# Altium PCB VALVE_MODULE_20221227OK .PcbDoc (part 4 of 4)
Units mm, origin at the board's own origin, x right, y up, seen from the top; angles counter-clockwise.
Board outline 260.15 x 142.01 mm, 2 copper layers (Top Layer, Bottom Layer); 455 components, 212 nets, 1302 pads, 385 vias.
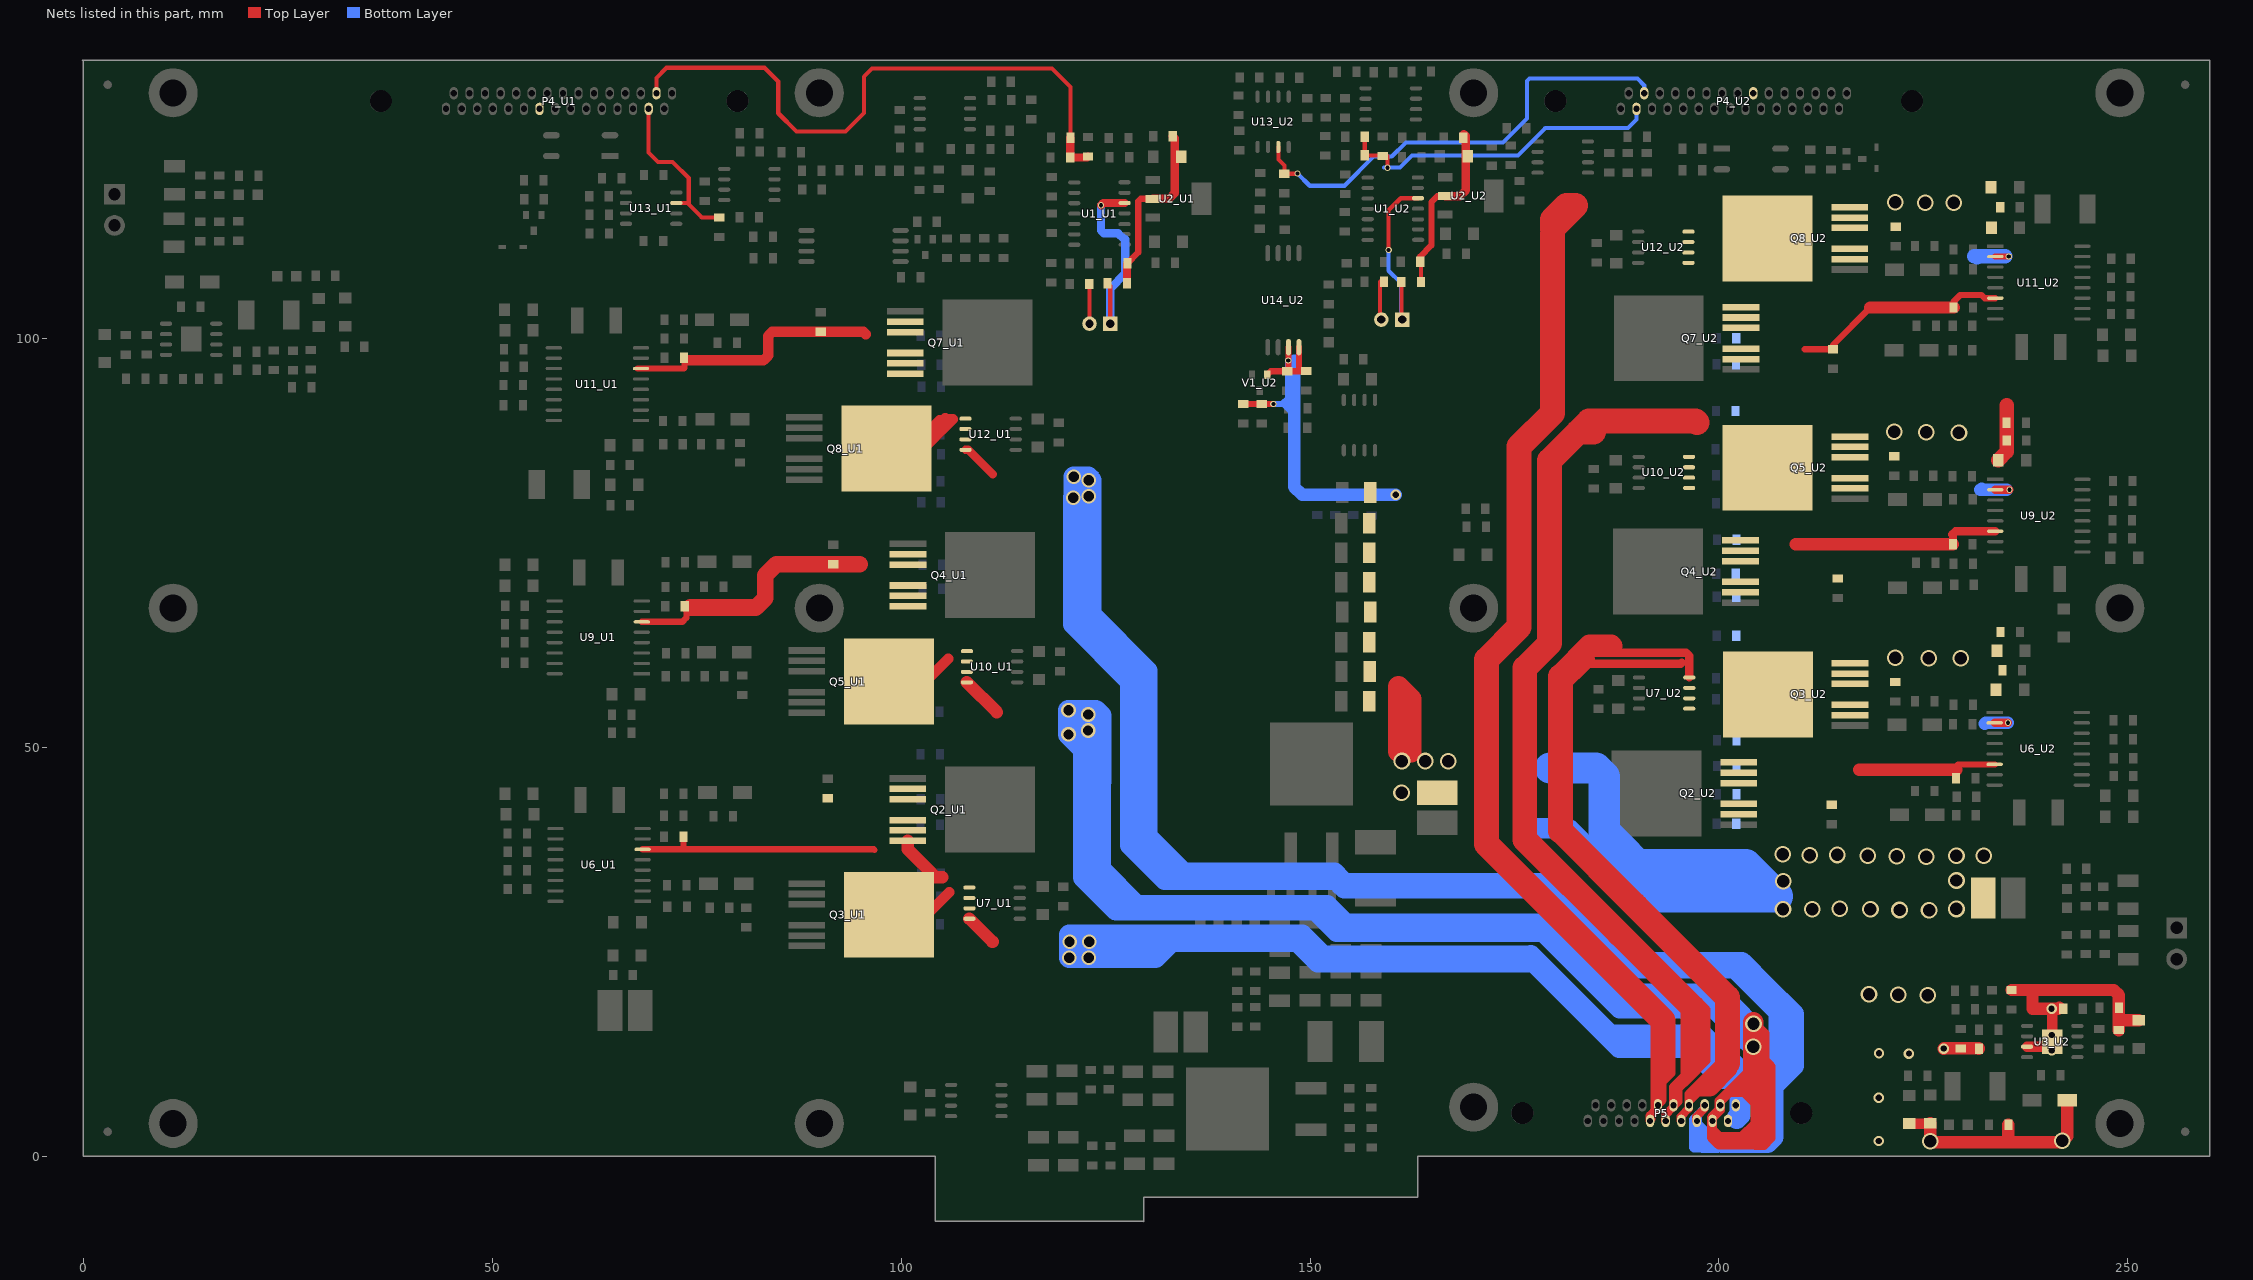
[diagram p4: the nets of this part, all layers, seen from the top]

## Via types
v1: diameter 0.762, hole 0.508, Top Layer to Bottom Layer, 142 vias
v2: diameter 2.032, hole 1.524, Top Layer to Bottom Layer, 140 vias
v3: diameter 1.27, hole 0.762, Top Layer to Bottom Layer, 77 vias
v4: diameter 1.27, hole 0.711, Top Layer to Bottom Layer, 14 vias
v5: diameter 1.778, hole 1.27, Top Layer to Bottom Layer, 12 vias

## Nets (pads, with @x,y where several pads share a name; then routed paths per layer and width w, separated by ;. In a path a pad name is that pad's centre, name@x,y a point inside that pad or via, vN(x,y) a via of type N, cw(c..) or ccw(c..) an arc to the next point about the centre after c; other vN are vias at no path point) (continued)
PGND_U2: C15_U2.2 C16_U2.2 C17_U2.2 C18_U2.2 C19_U2.2 C20_U2.2 C21_U2.2 C22_U2.2 C24_U2.2 C25_U2.1 C26_U2.1 C27_U2.1 C29_U2.1 C30_U2.1 C69_U2.1 C70_U2.2 C71_U2.2 C72_U2.2 C73_U2.2 C74_U2.2 C75_U2.2 C76_U2.2 C77_U2.2 C78_U2.2 C79_U2.2 C80_U2.2 C81_U2.2 C82_U2.2 C83_U2.2 C84_U2.2 C85_U2.2 C86_U2.2 C87_U2.2 C88_U2.2 C89_U2.2 C90_U2.2 C91_U2.2 C92_U2.2 C93_U2.2 C106_U2.2 C107_U2.2 C108_U2.2 C109_U2.2 C110_U2.2 C111_U2.2 C112_U2.2 C113_U2.2 D2_U2.1 Q3_U2.2 Q3_U2.3 Q3_U2.5 Q3_U2.6 Q3_U2.7 Q5_U2.2 Q5_U2.3 Q5_U2.5 Q5_U2.6 Q5_U2.7 Q8_U2.2 Q8_U2.3 Q8_U2.5 Q8_U2.6 Q8_U2.7 R16_U2.2 R21_U2.2 R22_U2.1 R24_U2.2 R25_U2.1 R37_U2.1 R54_U2.1 R68_U2.1 R76_U2.2 R80.2 U3_U2.7 U3_U2.9 U6_U2.2 U9_U2.2 U11_U2.2 U14_U2.3 U14_U2.4 V1_U2.1 | length 246.4
  Top Layer w0.762: C30_U2.1@141.859,91.948 C29_U2.1@144.12,91.948 145.517,91.948 145.542,91.973 v1(145.517,91.973) ; V1_U2.1@144.78,95.529 145.212,95.961 C69_U2.1@147.193,95.961 ; U14_U2.3@147.371,98.908 147.371,96.139 C69_U2.1@147.193,95.961 ; U14_U2.4@148.641,98.908 148.641,96.012 148.59,95.961 ; R76_U2.2@149.555,95.987 149.53,95.961 148.59,95.961 ; U11_U2.2@233.782,109.982 v1(235.433,109.982) ; C69_U2.1@147.193,95.961 148.59,95.961
  Top Layer w1.016: U6_U2.2@233.705,52.984 235.309,52.984 v1(235.32,52.995) ; U9_U2.2@233.782,81.483 v1(235.509,81.483)
  Top Layer w1.27: C22_U2.2@223.241,3.988 225.755,3.988 C21_U2.2@225.806,4.039 ; U3_U2.7@237.668,13.386 240.132,13.386 U3_U2.9@240.741,13.995 240.741,17.958 v3(240.665,18.034)
  Top Layer w1.524: C21_U2.2@225.806,4.039 225.806,1.829 225.933,1.702 235.356,1.702 ; v3(227.482,13.157) 227.508,13.183 R25_U2.1@229.54,13.183 231.75,13.183 C27_U2.1@231.775,13.157 ; R16_U2.2@235.382,3.861 235.382,1.727 235.356,1.702 ; R22_U2.1@235.763,20.32 237.922,20.32 ; C26_U2.1@241.605,18.161 241.478,18.034 v3(240.665,18.034) 238.328,18.034 238.328,19.914 237.922,20.32 ; D2_U2.1@242.57,6.858 242.57,2.438 241.833,1.702 235.356,1.702 ; C25_U2.1@248.869,15.418 248.869,16.535 ; C24_U2.2@251.333,16.612 248.945,16.612 248.869,16.535 ; 237.922,20.32 248.26,20.32 248.895,19.685 R24_U2.2@248.895,18.136 248.869,18.11 248.869,16.535
  Top Layer w1.778: C108_U2.2@234.137,85.09 235.204,86.157 235.204,91.796
  Top Layer w2.54: 160.807,49.479 160.807,57.429 162.331,55.905 162.331,49.378
  Bottom Layer w0.762: v1(145.517,91.973) 146.634,91.973 ; 148.057,90.627 146.71,91.973 ; 148.057,91.567 147.65,91.973 146.71,91.973 ; 148.057,97.257 148.031,97.282 v1(147.345,97.282) 147.345,92.685 146.634,91.973 ; 146.634,91.973 146.71,91.973
  Bottom Layer w1.524: 148.057,97.257 148.057,91.567 148.057,90.627 148.057,81.839 149.022,80.874 v3(160.477,80.874) ; 231.927,81.458 v1@235.204,81.458 ; 232.131,81.585 232.232,81.483 ; 232.512,52.883 232.624,52.995 v1(235.32,52.995)
  Bottom Layer w1.778: 231.216,110.033 234.975,110.033 ; 231.572,109.88 231.673,109.982
  Bottom Layer w2.54: 177.698,40.107 181.458,40.107 190.5,31.064 207.289,31.064
  Bottom Layer w3.81: 179.324,47.447 184.937,47.447 185.979,46.406 185.979,39.726 191.922,33.782 205.156,33.782 ; 190.043,35.662 203.276,35.662 207.162,31.775
  other v2: 225.831,1.829 241.986,1.88 225.501,19.685 221.894,19.736 218.338,19.812 225.679,30.048 222.072,30.099 207.823,30.175 218.516,30.175 211.404,30.201 229.032,30.226 214.782,30.251 207.848,33.63 229.032,33.706 225.349,36.627 221.742,36.678 229.032,36.728 218.186,36.754 232.359,36.754 211.074,36.779 214.452,36.83 207.797,36.906 161.188,44.45 166.878,48.285 161.239,48.311 164.109,48.311 225.654,60.858 229.54,60.858 221.564,60.96 229.337,88.468 225.349,88.519 221.412,88.57 225.222,116.561 228.702,116.561 221.564,116.611
  other v3: 219.532,1.854 219.532,7.137 223.215,12.548 219.558,12.573 240.69,12.929 240.69,14.834
PT1000_AN1_U1: P1_U1.2 R11_U1.1 | length 4.9
  Top Layer w0.508: R11_U1.1@123.012,106.629 123.038,106.604 P1_U1.2@123.038,101.778
PT1000_AN1_U2: P1_U2.2 R11_U2.1 | length 4.7
  Top Layer w0.508: R11_U2.1@158.547,106.909 158.547,102.464 P1_U2.2@158.725,102.286
PT1000_AP1_U1: P1_U1.1 R4_U1.2 U1_U1.12 | length 25.7
  Top Layer w0.508: R4_U1.2@125.247,106.731 125.578,106.401 P1_U1.1@125.578,101.778
  Top Layer w1.016: v1(124.435,116.256) 124.714,116.535 U1_U1.12@127.33,116.535
  Bottom Layer w1.016: v1(124.435,116.256) 124.435,113.182 124.79,112.827 126.543,112.827 127.254,112.116 127.406,112.116 127.406,107.925 125.578,106.096 P1_U1.1@125.578,101.778
PT1000_AP1_U2: P1_U2.1 R4_U2.2 U1_U2.12 | length 22.9
  Top Layer w0.508: v1(159.614,110.795) 159.614,115.646 161.087,117.119 U1_U2.12@163.195,117.119 ; R4_U2.2@161.163,106.883 161.163,102.387 P1_U2.1@161.265,102.286
  Bottom Layer w0.508: v1(159.614,110.795) 159.614,108.255 161.112,106.756 161.112,102.438 P1_U2.1@161.265,102.286
TEMP_U1: C12_U1.1 P4_U1.29 R5_U1.2 R9_U1.2 | length 76.1
  Top Layer w0.508: P4_U1.29@70.091,129.952 70.091,131.838 71.323,133.071 83.312,133.071 84.988,131.394 84.988,127.508 87.198,125.298 93.193,125.298 95.453,127.559 95.453,131.978 96.444,132.969 118.466,132.969 120.701,130.734 R9_U1.2@120.701,124.511
  Top Layer w1.016: R9_U1.2@120.701,124.511 120.701,122.123 R5_U1.2@120.675,122.098 122.733,122.098 C12_U1.1@122.86,122.225
TEMP_U2: C12_U2.1 P4_U2.29 R5_U2.2 R9_U2.2 | length 40.6
  Top Layer w0.508: R9_U2.2@156.693,124.638 R5_U2.2@156.693,122.352 157.836,122.352 158.826,122.352 C12_U2.1@158.902,122.276 ; v1(159.461,120.853) C12_U2.1@159.461,122.301
  Bottom Layer w0.508: 159.029,120.879 160.985,120.879 162.458,122.352 175.412,122.352 178.765,125.705 188.874,125.705 189.906,126.736 P4_U2.29@189.906,128.047
U_OUT_U1: C32_U1.2 Q2_U1.2 Q2_U1.3 Q2_U1.5 Q2_U1.6 Q2_U1.7 Q3_U1.4 R30_U1.2 U6_U1.6 U7_U1.1 U7_U1.2 | length 45.1
  Top Layer w0.762: U6_U1.6@68.402,37.516 73.508,37.516 ; C32_U1.2@73.406,39.04 73.406,37.617 73.508,37.516 ; 96.749,37.44 96.672,37.516 73.508,37.516
  Top Layer w1.27: Q3_U1.4@98.527,29.515 103.149,29.515 105.893,32.258
  Top Layer w1.524: Q2_U1.7@100.813,38.557 100.813,37.541 104.267,34.087 105.054,34.087
U_OUT_U2: C32_U2.2 Q2_U2.2 Q2_U2.3 Q2_U2.5 Q2_U2.6 Q2_U2.7 Q3_U2.4 R30_U2.2 U6_U2.6 U7_U2.1 U7_U2.2 | length 18.1
  Top Layer w0.762: C32_U2.2@228.981,46.228 228.981,47.244 228.981,47.65 229.235,47.904 U6_U2.6@233.705,47.904
  Top Layer w1.524: 217.145,47.269 217.17,47.244 228.981,47.244
UU_OUT1: P5.1 P5.11 U7_U1.3 U7_U1.4 | length 205.1
  Top Layer w1.524: U7_U1.4@108.356,29.032 111.15,26.238 111.227,26.238
  Bottom Layer w2.54: v5(122.961,24.257) v5@122.987,24.282 ; 176.987,24.536 186.944,14.58 ; 187.046,14.808 197.968,14.808 201.371,11.405 201.651,11.405 202.565,10.49 202.565,8.509 ; 202.159,4.597 202.565,5.004 202.565,8.509 ; v5(120.599,26.238) 120.599,27.076 149.022,27.076 151.587,24.511 176.581,24.511 177.343,23.749 ; v5(120.599,26.238) 120.599,24.308 v5(120.574,24.282) 131.115,24.282 133.071,26.238 ; v5(120.599,26.238) 133.071,26.238 ; 133.071,26.238 148.463,26.238 150.952,23.749 177.343,23.749 ; 177.343,23.749 187.833,13.259 196.596,13.259 200.355,9.5 201.574,9.5 202.565,8.509
  other v5: 122.987,26.213
UU_OUT2: P5.4 P5.14 U7_U2.3 U7_U2.4 | length 123.6
  Top Layer w1.016: 181.458,54.839 181.458,57.709 183.96,60.211 ; P5.14@195.332,4.318 195.332,4.858 196.285,5.81 196.285,6.223 P5.4@196.285,6.649 ; 195.453,60.35 195.313,60.211 183.96,60.211 ; U7_U2.4@196.367,58.522 196.367,61.163 195.961,61.57 183.617,61.57 184.353,60.833 184.353,60.604 183.96,60.211 ; 197.383,7.747 P5.4@196.285,6.649 ; 198.298,8.661 197.46,7.823 198.755,7.823 ; 198.857,9.246 198.603,9.246 197.79,8.433 197.104,8.433 ; 201.016,11.405 200.076,11.405 197.104,8.433 ; P5.4@196.285,6.649 196.285,7.614 197.104,8.433
  Top Layer w2.54: 183.185,61.138 183.185,60.427 180.721,57.963 180.721,59.03 184.175,62.484 ; 184.226,62.433 184.175,62.484 ; 186.919,62.382 186.817,62.484 184.175,62.484 ; 198.831,8.585 200.99,10.744
  Top Layer w3.048: 180.645,58.623 180.645,39.776 189.586,30.836 ; 189.916,30.505 189.586,30.836 ; 201.016,11.405 201.016,19.406 189.586,30.836
V_OUT_U1: C47_U1.1 Q4_U1.2 Q4_U1.3 Q4_U1.5 Q4_U1.6 Q4_U1.7 Q5_U1.4 R47_U1.1 U9_U1.6 U10_U1.1 U10_U1.2 | length 40.2
  Top Layer w0.762: U9_U1.6@68.301,65.329 73.279,65.329 73.762,65.811 73.762,67.031 C47_U1.1@73.558,67.234 ; 94.945,72.365 95.199,72.111
  Top Layer w1.27: Q5_U1.4@98.857,58.014 102.946,58.014 105.766,60.833
  Top Layer w2.032: 74.219,67.081 82.245,67.081 83.414,68.25 83.414,71.044 84.734,72.365 R47_U1.1@91.694,72.365 94.945,72.365
V_OUT_U2: C47_U2.1 Q4_U2.2 Q4_U2.3 Q4_U2.5 Q4_U2.6 Q4_U2.7 Q5_U2.4 R47_U2.1 U9_U2.6 U10_U2.1 U10_U2.2 | length 26.2
  Top Layer w0.762: 209.118,74.574 209.372,74.828
  Top Layer w1.016: C47_U2.1@228.6,74.828 228.6,75.895 228.498,75.997 228.905,76.403 U9_U2.6@233.782,76.403
  Top Layer w1.524: 209.372,74.828 C47_U2.1@228.6,74.828
VAL_CTRL_U1: P4_U1.7
VAL_CTRL_U2: P4_U2.7
VDC1_U1: P4_U1.14 R77_U1.2 U13_U1.7 | length 20.6
  Top Layer w0.508: P4_U1.14@69.139,128.047 69.139,122.707 70.282,121.564 72.06,121.564 74.041,119.583 74.041,116.51 ; U13_U1.7@72.517,116.535 73.889,116.535 75.641,114.783 R77_U1.2@77.775,114.783
VDC1_U2: P4_U2.14 R77_U2.2 U13_U2.7 | length 57.6
  Top Layer w0.508: U13_U2.7@146.126,123.393 146.126,121.869 146.863,121.133 R77_U2.2@146.863,120.117 148.438,120.117 v1(148.463,120.142)
  Bottom Layer w0.508: v1(148.463,120.142) 149.962,118.643 154.203,118.643 157.785,122.225 159.995,122.225 161.722,123.952 173.609,123.952 176.53,126.873 176.53,131.445 176.835,131.75 190.017,131.75 190.858,130.909 P4_U2.14@190.858,129.952
VREF_2V5_U1: C2_U1.1 C3_U1.1 R3_U1.1 R4_U1.1 U2_U1.2 | length 22.5
  Top Layer w0.762: R3_U1.1@127.686,109.169 129.007,110.49 129.007,116.738 129.311,117.043 U2_U1.2@130.785,117.043
  Top Layer w1.016: R4_U1.1@127.635,106.731 127.635,109.118 R3_U1.1@127.686,109.169 ; U2_U1.2@130.785,117.043 132.766,117.043 133.452,117.729 133.452,124.46 C3_U1.1@133.223,124.689
VREF_2V5_U2: C2_U2.1 C3_U2.1 R3_U2.1 R4_U2.1 U2_U2.2 | length 22.1
  Top Layer w0.508: R3_U2.1@163.474,109.347 163.551,109.271 R4_U2.1@163.551,106.883
  Top Layer w0.762: R3_U2.1@163.474,109.347 163.474,109.982 164.846,111.354 164.846,116.653 165.566,117.373 U2_U2.2@166.522,117.373
  Top Layer w1.016: U2_U2.2@166.522,117.373 168.326,117.373 169.037,118.085 169.037,124.739 C3_U2.1@168.808,124.968
VV_OUT1: P5.2 P5.12 U10_U1.3 U10_U1.4 | length 353.3
  Top Layer w1.27: 202.59,8.23 204.013,9.652 ; 203.429,10.058 203.022,9.652 ; 203.556,10.236 v2@203.556,15.443 ; v2@204.165,16.358 204.191,16.332 205.537,14.986 205.537,11.709 206.273,10.973 206.273,9.627 ; 204.191,9.652 204.013,9.652 ; 204.47,9.373 204.47,8.966 ; 205.588,9.83 205.588,9.677 ; 205.969,9.627 206.273,9.322 ; 199.142,2.305 200,1.448 204.445,1.448 ; 199.142,2.305 199.142,3.213 ; 199.142,2.305 200.05,2.305 ; 199.142,3.213 199.142,4.318 199.142,4.731 200.095,5.683 200.095,6.223 200.095,6.725 201.244,7.874 ; 199.142,3.213 200.05,2.305 ; 200.05,2.305 202.794,2.305 ; 201.244,7.874 203.098,7.874 ; 201.244,7.874 203.022,9.652 ; 202.794,2.305 204.47,3.981 204.47,6.502 ; 202.794,2.305 204.184,2.305 205.334,3.454 ; 203.022,9.652 204.013,9.652 ; 203.098,7.874 204.47,6.502 ; 203.098,7.874 203.86,7.874 ; 203.86,7.874 204.47,7.264 ; 203.86,7.874 204.47,7.874 ; 204.013,9.652 204.191,9.83 204.191,11.709 206.273,9.627 ; 204.445,1.448 205.334,2.337 205.334,3.454 ; 204.445,1.448 204.47,1.422 205.461,1.422 206.273,2.235 206.273,9.322 ; 204.47,6.502 204.47,7.264 ; 204.47,7.264 204.47,7.874 ; 204.47,7.264 205.334,6.401 ; 204.47,7.874 204.47,8.966 ; 204.47,7.874 205.207,7.874 ; 204.47,8.966 204.876,8.966 205.588,9.677 ; 205.207,7.874 205.334,7.747 205.334,6.401 ; 205.207,7.874 205.588,8.255 205.588,9.677 ; 205.334,3.454 205.334,6.401 ; 206.273,9.322 206.273,9.627
  Top Layer w1.524: U10_U1.4@108.052,57.937 111.709,54.28
  Top Layer w2.54: 204.191,9.83 204.191,9.652 ; 204.191,11.709 v2(204.191,13.386) v2@204.191,16.332 ; 204.47,7.874 204.191,8.153 204.191,9.246 ; 204.47,8.966 204.191,9.246 ; 204.876,8.966 204.47,9.373 204.191,9.652 ; 204.191,9.246 204.191,9.652
  Bottom Layer w2.54: v5(122.86,52.045) v5@122.885,52.07 ; 197.879,19.672 202.717,14.834 ; v2@204.178,13.373 202.997,14.554 ; v2(204.191,13.386) 204.191,15.697 202.997,16.891 ; v5(120.472,51.562) v5(120.472,54.534) ; v5(120.472,51.562) 122.301,49.733 122.301,34.061 124.384,31.979 ; v5(120.472,51.562) v5@123.444,51.562 ; v5(120.472,54.534) v5@123.444,51.562 ; v5(120.472,54.534) 123.8,54.534 124.46,53.873 124.46,45.745 124.384,45.669 ; v5@123.444,51.562 123.571,51.562 124.384,50.749 ; v5@123.444,51.562 124.257,50.749 124.384,50.749 ; 124.384,31.979 126.263,30.099 150.647,30.099 ; 124.384,31.979 124.384,35.103 ; 124.384,35.103 124.384,45.669 ; 124.384,35.103 128.803,30.683 152.07,30.683 154.33,28.423 ; 124.384,45.669 124.384,50.749 ; 150.647,30.099 151.282,30.099 152.959,28.423 ; 150.647,30.099 153.264,27.483 153.899,27.483 ; 152.959,28.423 153.899,27.483 ; 152.959,28.423 154.33,28.423 ; 153.899,27.483 178.511,27.483 ; 154.33,28.423 178.181,28.423 179.121,27.483 ; 178.511,27.483 179.121,27.483 ; 178.511,27.483 187.909,18.085 201.803,18.085 202.717,17.17 ; 179.121,27.483 186.741,19.863 200.127,19.863 202.717,17.272 202.717,17.17 ; 202.717,14.834 202.997,14.554 ; 202.717,14.834 202.717,17.17 ; 202.717,17.17 202.997,16.891 ; 202.997,14.554 202.997,16.891
  other v2: 204.216,16.205
  other v5: 122.885,54
VV_OUT2: P5.5 P5.15 U10_U2.3 U10_U2.4 | length 141.4
  Top Layer w1.016: P5.15@193.427,4.318 193.427,5.068 P5.5@194.38,6.021 ; 196.799,12.243 196.317,11.76 ; 196.799,14.173 195.809,13.183 195.809,11.252 ; 196.799,18.186 198.476,16.51 ; 197.18,19.228 198.476,17.932 198.476,16.51 ; P5.5@194.38,6.021 194.38,6.223 194.38,7.588 ; P5.5@194.38,6.021 195.008,6.649 195.008,8.217 ; 194.38,7.588 194.38,8.452 195.809,9.881 195.809,11.252 ; 194.38,7.588 195.008,8.217 ; 195.008,8.217 196.317,9.525 ; 195.809,11.252 196.317,11.76 ; 196.317,9.525 196.317,9.906 ; 196.317,9.525 198.476,11.684 198.476,12.065 ; 196.317,9.906 198.476,12.065 ; 196.317,9.906 196.317,11.76 ; 198.476,12.065 198.476,16.51
  Top Layer w3.048: 182.778,88.544 184.633,88.544 ; 187.909,27.076 187.731,27.254 ; 196.799,12.243 196.799,14.173 196.799,18.186 187.731,27.254 ; 197.307,89.687 197.104,89.891 184.125,89.891 179.299,85.065 179.299,62.713 176.251,59.665 176.251,38.735 187.731,27.254
W_OUT_U1: C54_U1.1 Q7_U1.2 Q7_U1.3 Q7_U1.5 Q7_U1.6 Q7_U1.7 Q8_U1.4 R62_U1.1 U11_U1.6 U12_U1.1 U12_U1.2 | length 47.3
  Top Layer w0.762: U11_U1.6@67.767,96.291 73.431,96.291 73.533,96.393 73.533,97.409 C54_U1.1@73.457,97.485
  Top Layer w1.27: C54_U1.1@73.66,97.333 83.185,97.333 83.744,97.892 83.744,100.279 84.252,100.787 R62_U1.1@90.17,100.787 95.377,100.787 95.682,100.482 ; Q8_U1.4@98.222,86.512 Q8_U1.4@101.295,86.512 ; 104.75,89.967 Q8_U1.4@101.295,86.512 ; 105.41,90.246 105.537,90.119 106.299,90.119 102.692,86.512 Q8_U1.4@101.295,86.512
W_OUT_U2: C54_U2.1 Q7_U2.2 Q7_U2.3 Q7_U2.5 Q7_U2.6 Q7_U2.7 Q8_U2.4 R62_U2.1 U11_U2.6 U12_U2.1 U12_U2.2 | length 26.9
  Top Layer w0.762: 210.49,98.654 R62_U2.1@213.944,98.654 213.944,99.187 218.516,103.759 ; C54_U2.1@228.676,103.759 228.676,104.496 229.464,105.283 232.105,105.283 232.486,104.902 U11_U2.6@233.782,104.902
  Top Layer w1.524: 218.516,103.759 C54_U2.1@228.676,103.759
WW_OUT1: P5.3 P5.13 U12_U1.3 U12_U1.4 | length 361.7
  Top Layer w1.016: U12_U1.4@107.874,86.36 108.229,86.36 111.227,83.363 ; P5.13@197.237,4.318 197.237,4.832 198.19,5.785 P5.3@198.19,6.223
  Bottom Layer w1.016: 197.891,1.829 197.409,2.311 P5.13@197.409,4.002 ; P5.3@198.19,6.223 198.19,5.836 P5.13@197.409,5.055 ; P5.13@196.85,3.931 197.237,4.318 197.237,4.173 P5.13@197.409,4.002 ; P5.13@196.85,3.931 196.85,1.067 196.952,0.965 199.695,0.965 200.406,1.676 199.734,1.676 P5.13@197.409,4.002 ; P5.13@196.85,3.931 196.85,4.496 P5.13@197.409,5.055 ; P5.13@197.409,4.002 P5.13@197.409,5.055
  Bottom Layer w2.54: v5(121.056,80.518) 121.056,65.049 128.067,58.039 128.067,38.024 132.283,33.807 153.797,33.807 ; v5(121.107,83.058) 121.107,80.569 121.26,80.721 121.26,83.058 122.86,83.058 123.266,82.652 123.266,66.167 130.073,59.36 130.073,39.116 134.569,34.62 152.984,34.62 153.797,33.807 ; v5(122.936,80.67) v5@122.961,80.696 ; 188.468,23.495 190.805,23.673 ; 197.714,2.261 197.891,2.083 197.891,1.829 198.044,1.676 199.734,1.676 ; 200.406,1.676 204.064,1.676 ; 153.797,33.172 153.797,33.807 ; 153.797,33.172 153.949,33.325 154.28,33.325 ; 153.797,33.172 154.178,32.791 154.813,32.791 ; 153.797,33.172 154.432,33.172 ; 153.797,33.807 154.28,33.325 ; 154.28,33.325 154.432,33.172 ; 154.28,33.325 178.689,33.325 ; 154.432,33.172 157.937,33.172 158.318,32.791 ; 154.432,33.172 154.813,32.791 ; 154.813,32.791 158.318,32.791 ; 158.318,32.791 178.689,32.791 ; 178.689,32.791 178.689,32.69 181.305,30.074 ; 178.689,32.791 178.689,33.325 ; 178.689,32.791 179.172,32.791 181.305,30.658 ; 178.689,33.325 181.305,30.709 181.305,30.658 ; 181.305,30.074 181.305,30.658 ; 181.305,30.074 188.366,23.012 191.287,23.012 ; 181.305,30.658 188.29,23.673 190.805,23.673 ; 190.805,23.673 202.794,23.673 205.715,20.752 ; 190.805,23.673 191.287,23.19 191.287,23.012 ; 191.287,23.012 201.93,23.012 205.715,19.228 ; 204.064,1.676 205.638,3.251 ; 204.064,1.676 205.918,1.676 206.604,2.362 206.604,4.216 ; 205.638,3.251 205.638,10.363 207.315,12.04 ; 205.638,3.251 206.604,4.216 ; 205.715,19.228 205.715,20.752 ; 205.715,19.228 207.315,17.628 207.315,12.04 ; 205.715,20.752 209.093,17.374 209.093,11.049 207.315,9.271 ; 206.604,4.216 206.604,8.56 207.315,9.271 ; 207.315,9.271 207.315,12.04
  other v5: 122.961,82.626
WW_OUT2: P5.6 P5.16 U12_U2.3 U12_U2.4 | length 146.3
  Top Layer w1.016: 192.145,11.398 192.145,5.582 ; 193.167,10.973 192.475,10.281 192.475,8.452 ; 194.177,12.465 194.177,10.154 193.078,9.055 ; 191.745,5.182 191.745,4.54 191.522,4.318 191.522,4.959 191.745,5.182 ; 191.745,5.182 192.145,5.582 ; 192.145,5.582 192.475,5.912 P5.6@192.475,6.223 ; P5.6@192.475,6.223 192.475,8.452 ; P5.6@192.475,6.223 193.078,6.826 193.078,9.055 ; 192.475,8.452 193.078,9.055
  Top Layer w3.048: 179.629,112.776 179.629,90.83 175.565,86.766 175.565,64.694 171.577,60.706 171.577,38.176 186.487,23.266 ; 187.617,22.136 186.487,23.266 ; 193.167,10.973 193.167,16.586 186.487,23.266 ; 179.629,113.386 182.474,116.23 181.356,116.23 179.629,114.503 179.629,113.386
pads on no net: P4_U1. P4_U1.9 P4_U1.10 P4_U1.22 P4_U1.24 P4_U1.25 P4_U2. P4_U2.9 P4_U2.10 P4_U2.22 P4_U2.24 P4_U2.25 P5. U1_U1.5 U1_U1.6 U1_U1.7 U1_U2.5 U1_U2.6 U1_U2.7 U2_U1.4 U2_U2.4 U5_U1.6 U5_U2.6 U6_U1.4 U6_U1.5 U6_U1.9 U6_U1.10 U6_U1.16 U6_U2.4 U6_U2.5 U6_U2.9 U6_U2.10 U6_U2.16 U7_U1.6 U7_U2.6 U9_U1.4 U9_U1.5 U9_U1.9 U9_U1.10 U9_U1.16 U9_U2.4 U9_U2.5 U9_U2.9 U9_U2.10 U9_U2.16 U10_U1.6 U10_U2.6 U11_U1.4 U11_U1.5 U11_U1.9 U11_U1.10 U11_U1.16 U11_U2.4 U11_U2.5 U11_U2.9 U11_U2.10 U11_U2.16 U12_U1.6 U12_U2.6

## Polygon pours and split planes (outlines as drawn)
AGND_U2 on Top Layer "Top Layer-No Net" (solid, remove dead copper, pour order 8): 140.995,133.987 140.995,112.89 144.374,109.512 144.704,109.182 153.391,109.182 153.391,91.884 153.924,91.351 154.051,91.224 158.623,91.224 158.623,106.057 158.547,106.134 158.547,108.318 171.628,108.318 171.679,108.267 173.279,109.867 173.279,114.287 173.533,114.287 178.918,119.672 179.172,119.926 199.187,119.926 199.187,133.642 199.39,133.845 199.248,133.987 175.209,133.987 175.209,125.946 175.26,125.895 175.006,126.149 164.846,126.149 164.846,133.911 164.922,133.987 140.995,133.987
AGND_U1 on Top Layer "Top Layer-No Net" (solid, remove dead copper, pour order 6): 63.5,133.985 63.5,112.09 87.579,112.09 87.681,111.989 87.732,112.039 90.983,112.039 90.983,114.91 91.135,115.062 94.336,118.262 94.336,118.491 113.817,118.491 116.281,116.027 117.399,116.027 117.399,106.985 117.932,106.451 118.593,105.791 127.229,105.791 137.795,105.791 137.998,105.588 138.151,105.74 138.151,133.985 95.961,133.985 95.758,134.188 95.123,133.553 95.123,125.451 84.684,125.451 84.633,125.4 84.633,133.985 63.5,133.985
PGND_U1 on Top Layer "Top Layer-No Net" (solid, remove dead copper, pour order 11): -0.102,108.382 0,108.28 0,73.711 35.56,73.711 35.535,73.736 35.535,108.28 0.025,108.28 0,108.306
PGND_U2 on Top Layer "Top Layer-No Net" (solid, remove dead copper, pour order 13): 217.322,20.991 217.322,0.086 217.373,0.036 244.653,0.036 244.653,21.016 244.704,21.067 244.653,21.016 217.399,21.016
AGND_U2 on Bottom Layer "Top Layer-No Net" (solid, remove dead copper, pour order 7): 141.07,133.702 141.07,112.605 144.448,109.227 144.778,108.897 153.465,108.897 153.465,91.6 153.998,91.066 154.125,90.939 158.697,90.939 158.697,105.773 158.621,105.849 158.621,108.033 171.702,108.033 171.753,107.983 173.353,109.583 173.353,114.002 173.607,114.002 178.992,119.387 179.246,119.641 199.261,119.641 199.261,133.357 199.464,133.56 199.322,133.702 175.284,133.702 175.284,125.661 175.334,125.61 175.08,125.864 164.92,125.864 164.92,133.626 164.997,133.702 141.07,133.702
AGND_U1 on Bottom Layer "Top Layer-No Net" (solid, remove dead copper, pour order 5): 63.57,133.964 63.57,112.069 87.65,112.069 87.751,111.968 87.802,112.018 91.053,112.018 91.053,114.889 91.206,115.041 94.406,118.241 94.406,118.47 113.888,118.47 116.352,116.006 117.469,116.006 117.469,106.964 118.003,106.43 118.663,105.77 127.299,105.77 137.865,105.77 138.069,105.567 138.221,105.719 138.221,133.964 96.032,133.964 95.828,134.167 95.193,133.532 95.193,125.43 84.754,125.43 84.703,125.379 84.703,133.964 63.57,133.964

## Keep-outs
Keep-Out Layer:
  lines w0.254: -0.003,3 ccw(c2.997,3) 2.997,0 104.2,0 104.2,-8.001 129.7,-8.001 129.7,-5 ; 0,3 0,130.988 cw(c3,130.988) 3,133.988 ; 3,134 256.997,134 ; 129.692,-5 163.2,-5 163.2,0 256.997,0 ccw(c256.997,3) 259.997,3 ; 257,134.01 cw(c257,131.01) 260,131.01 260,2.972

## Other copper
Top Layer:
  rectangle net ISO_GND_U2: 244.246,32.283 251.308,36.728
  rectangle net NetC13_U1_1: 13.97,102.87 20.98,108.407
  rectangle net PGND_U1: 11.963,94.005 14.757,100.787
  rectangle net ISO_GND_U2: 249.352,96.774 253.263,112.014
  rectangle net ISO_GND_U2: 249.86,72.39 253.416,84.76
  rectangle net ISO_GND_U2: 249.961,40.589 253.314,55.753
  rectangle net PGND_U2: 217.246,18.237 226.39,31.064
  rectangle net ISO_GND_U2: 234.29,22.682 240.36,37.719
  rectangle net ISO_+15V_U2: 254.051,29.743 259.309,116.865
  rectangle net ISO_+15VD_U2: 235.991,112.446 240.589,119.304
  rectangle net PGND_U2: 238.912,12.268 242.341,20.828
  rectangle net NetC13_U2_1: 232.918,5.969 236.55,11.43
  rectangle net NetC13_U2_1: 235.356,5.969 238.43,12.446
  rectangle net ISO_GND_U2: 239.268,22.682 257.099,25.502
  rectangle net ISO_+15V_U2: 241.63,26.518 259.563,31.09
  rectangle net ISO_GND_U1: 48.438,55.677 52.299,73.355
  rectangle net ISO_GND_U1: 48.59,88.036 52.121,104.343
  rectangle net ISO_GND_U1: 41.021,18.237 52.375,45.364
  rectangle net ISO_GND_U1: 37.44,17.882 44.069,103.124
  rectangle net ISO_GND_U1: 37.389,13.132 65.862,20.371
  rectangle net HVCC_IN_U1: 146.101,7.341 152.832,16.612
  rectangle net HVCC_IN_U1: 146.101,7.315 158.496,10.363
  rectangle net NetQ1_U1_1: 148.158,2.464 158.471,6.375
  rectangle net HVCCIN_U1: 115.341,0.762 138.862,8.636
  rectangle net HVCC_U1: 110.846,7.01 114.148,14.707
  rectangle net HVCC_U1: 105.131,10.592 114.148,15.088
  rectangle net U_OUT_U1: 92.939,26.848 103.2,45.364
  rectangle net V_OUT_U1: 94.209,57.455 103.175,74.016
  rectangle net W_OUT_U1: 92.989,88.849 102.946,102.464
  rectangle net U_OUT_U1: 99.695,31.217 109.652,35.408
  rectangle net V_OUT_U1: 99.543,60.02 109.474,64.465
  rectangle net W_OUT_U1: 97.739,88.595 108.61,92.786
  rectangle net U_OUT_U1: 72.873,37.338 93.243,39.954
  rectangle net U_OUT_U1: 89.23,38.786 93.751,44.653
  rectangle net W_OUT_U1: 83.058,96.672 93.675,101.549
  rectangle net PGND_U1: 118.948,10.566 133.883,17.729
  rectangle net PGND_U1: 109.068,-2.464 133.579,0.025
  rectangle net PGND_U1: 82.652,21.412 90.907,32.487
  rectangle net PGND_U1: 67.208,12.167 83.21,28.778
  rectangle net PGND_U1: 66.548,49.86 83.083,57.201
  rectangle net PGND_U1: 82.525,49.835 90.78,60.909
  rectangle net PGND_U1: 66.675,77.521 82.804,85.623
  rectangle net PGND_U1: 82.245,77.521 90.5,89.332
  rectangle net UU_OUT1: 106.045,23.241 109.652,30.709
  rectangle net UU_OUT1: 106.477,23.241 123.901,27.153
  rectangle net VV_OUT1: 105.766,51.664 109.55,59.461
  rectangle net VV_OUT1: 105.766,50.521 123.901,55.626
  rectangle net WW_OUT1: 105.613,79.426 109.753,87.986
  rectangle net WW_OUT1: 108.941,79.426 123.876,84.099
  rectangle net HVCC_IN: 140.157,17.475 166.827,20.041
  rectangle net HVCC_IN: 156.032,11.201 183.718,19.152
  rectangle net PGND: 134.518,21.387 158.801,26.899
  rectangle net PGND: 134.518,13.31 139.395,22.809
  rectangle net PGND: 134.518,12.979 145.39,16.637
  rectangle net HVCCIN_U1: 110.947,1.6 115.875,6.401
  rectangle net HVCC_IN: 135.763,27.737 164.744,30.886
  rectangle net HVCC_IN_U2: 151.892,34.468 160.553,40.615
  rectangle net U_OUT_U2: 200.025,41.275 211.455,61.874
  rectangle net V_OUT_U2: 200.228,68.529 211.455,89.865
  rectangle net W_OUT_U2: 200.025,97.028 211.963,117.907
  rectangle net PGND_U2: 213.69,109.245 219.304,117.805
  rectangle net PGND_U2: 216.992,112.319 234.95,117.78
  rectangle net W_OUT_U2: 211.582,98.12 219.177,105.156
  rectangle net V_OUT_U2: 207.239,69.367 218.516,76.429
  rectangle net PGND_U2: 213.69,81.255 219.456,92.812
  rectangle net PGND_U2: 217.526,84.607 235.661,92.786
  rectangle net PGND_U2: 213.639,57.023 234.975,64.516
  rectangle net PGND_U2: 213.639,53.492 219.456,61.976
  rectangle net U_OUT_U2: 207.899,42.139 219.862,49.124
  rectangle net HVCCIN_U2: 144.983,44.552 155.55,87.401
  rectangle net W_OUT_U2: 194.945,106.477 202.819,110.846
  rectangle net WW_OUT2: 194.869,111.404 198.526,117.831
  rectangle net WW_OUT2: 181.356,114.681 198.45,117.831
  rectangle net V_OUT_U2: 194.97,78.435 202.971,83.261
  rectangle net VV_OUT2: 194.97,83.922 198.857,90.957
  rectangle net VV_OUT2: 183.363,86.944 198.831,91.034
  rectangle net U_OUT_U2: 194.945,51.283 201.066,56.363
  rectangle net UU_OUT2: 194.767,56.896 199.288,63.144
  rectangle net UU_OUT2: 184.76,59.792 199.288,63.805
  rectangle net PGND_U2: 156.743,42.901 165.633,83.109
  rectangle net HVCC_U2: 166.675,92.05 177.19,96.19
  rectangle net HVCC_U2: 166.649,94.92 177.19,105.74
  rectangle net PGND_U2: 206.299,28.931 233.832,39.014
  rectangle net PGND_U2: 159.791,42.951 168.021,61.163
  rectangle net HVCC_U2: 156.388,83.795 172.771,87.452
  rectangle net HVCC_U2: 162.027,84.557 172.771,96.723
  rectangle net ISO_+15V_U1: 9.525,113.513 19.812,118.364
  rectangle net NetC13_U1_1: 15.392,101.346 21.006,105.004
  rectangle net NetC21_U1_1: 24.968,97.866 32.868,102.184
  rectangle net ISO_GND_U1: 7.645,118.948 19.71,123.749
  rectangle net ISO_+15V_U2: 214.986,124.663 220.675,131.445
  pour cut-out: 18.796,105.867 18.669,105.74 18.669,99.847 26.746,99.847 26.721,99.873 26.721,105.842 18.72,105.842
Bottom Layer:
  rectangle net ISO_GND_U2: 225.933,127.178 244.526,133.325
  rectangle net ISO_GND_U2: 245.796,36.093 255.219,62.281
  rectangle net ISO_GND_U2: 248.945,72.415 256.464,123.495
  rectangle net ISO_GND_U2: 253.721,31.013 259.385,123.52
  rectangle net ISO_GND_U2: 238.912,30.836 259.182,37.897
  rectangle net ISO_GND_U2: 238.938,22.784 253.162,37.668
  rectangle net PGND_U2: 217.221,0.533 244.577,21.006
  rectangle net AGND_U1: 123.012,87.376 138.532,91.186
  rectangle net +5VA_U1: 119.812,91.694 135.712,93.955
  rectangle net ISO_GND_U1: 41.656,55.651 49.962,73.355
  rectangle net ISO_GND_U1: 39.218,88.036 50.089,97.968
  rectangle net ISO_GND_U1: 37.465,13.233 52.426,45.187
  rectangle net ISO_GND_U1: 37.414,13.233 44.679,123.647
  rectangle net ISO_GND_U1: 7.645,110.033 44.704,123.8
  rectangle net HVCC_U1: 105.029,10.541 116.942,103.454
  rectangle net PGND_U1: 119.024,-2.489 129.921,17.704
  rectangle net PGND_U1: 105.435,-2.464 126.568,9.627
  rectangle net PGND_U1: 94.59,1.219 113.03,9.627
  rectangle net PGND_U1: 67.183,8.992 102.26,62.484
  rectangle net PGND_U1: 67.107,72.542 102.184,103.505
  rectangle net PGND_U1: 67.183,58.826 85.623,82.22
  rectangle net PGND_U1: 94.336,59.055 102.184,75.209
  rectangle net PGND: 134.544,1.321 148.006,23.774
  rectangle net PGND: 145.466,10.109 176.327,18.898
  rectangle net PGND: 136.728,1.321 165.379,12.243
  rectangle net PGND: 179.172,2.718 186.588,10.643
  rectangle net HVCC_U2: 186.715,49.987 200.228,105.816
  rectangle net HVCC_U2: 174.904,86.995 187.452,105.74
  rectangle net PGND_U2: 201.6,28.905 233.832,117.729
  rectangle net PGND_U2: 206.324,28.931 233.807,34.442
  rectangle net HVCC_U2: 190.17,39.7 200.279,52.273
  rectangle net PGND_U2: 156.87,38.557 184.556,49.403
  rectangle net PGND_U2: 183.871,35.839 188.595,46.812
  rectangle net PGND_U1: 1.473,73.736 35.56,108.356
